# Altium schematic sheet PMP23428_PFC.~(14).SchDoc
size 431 x 279 mm; Date: Not shown in title block; ApprovedBy: Not shown in title block; CheckedBy: Not shown in title block; Author: Not shown in title block; CompanyName: Not shown in title block; Engineer: Not shown in title block; Organization: Not shown in title block; Address1: Not shown in title block; Address2: Not shown in title block; Address3: Not shown in title block; Address4: Not shown in title block; DocumentNumber: 1; Revision: Use project parameter SCH_Rev; SheetNumber: 1; SheetTotal: 4; PageSetup: Record=PageOptions¦CenterHorizontal=True¦CenterVertical=True¦PrintScale=1.00¦XCorrection=1.00¦YCorrection=1.00¦PrintKind=0¦BorderSize=5000000¦LeftOffset=0¦BottomOffset=0¦Orientation=2¦PaperLength=1000¦PaperWidth=1000¦Scale=100¦PaperSource=15¦PrintQuality=600¦MediaType=1¦DitherType=10¦PaperKind=Letter¦PrintScaleMode=1
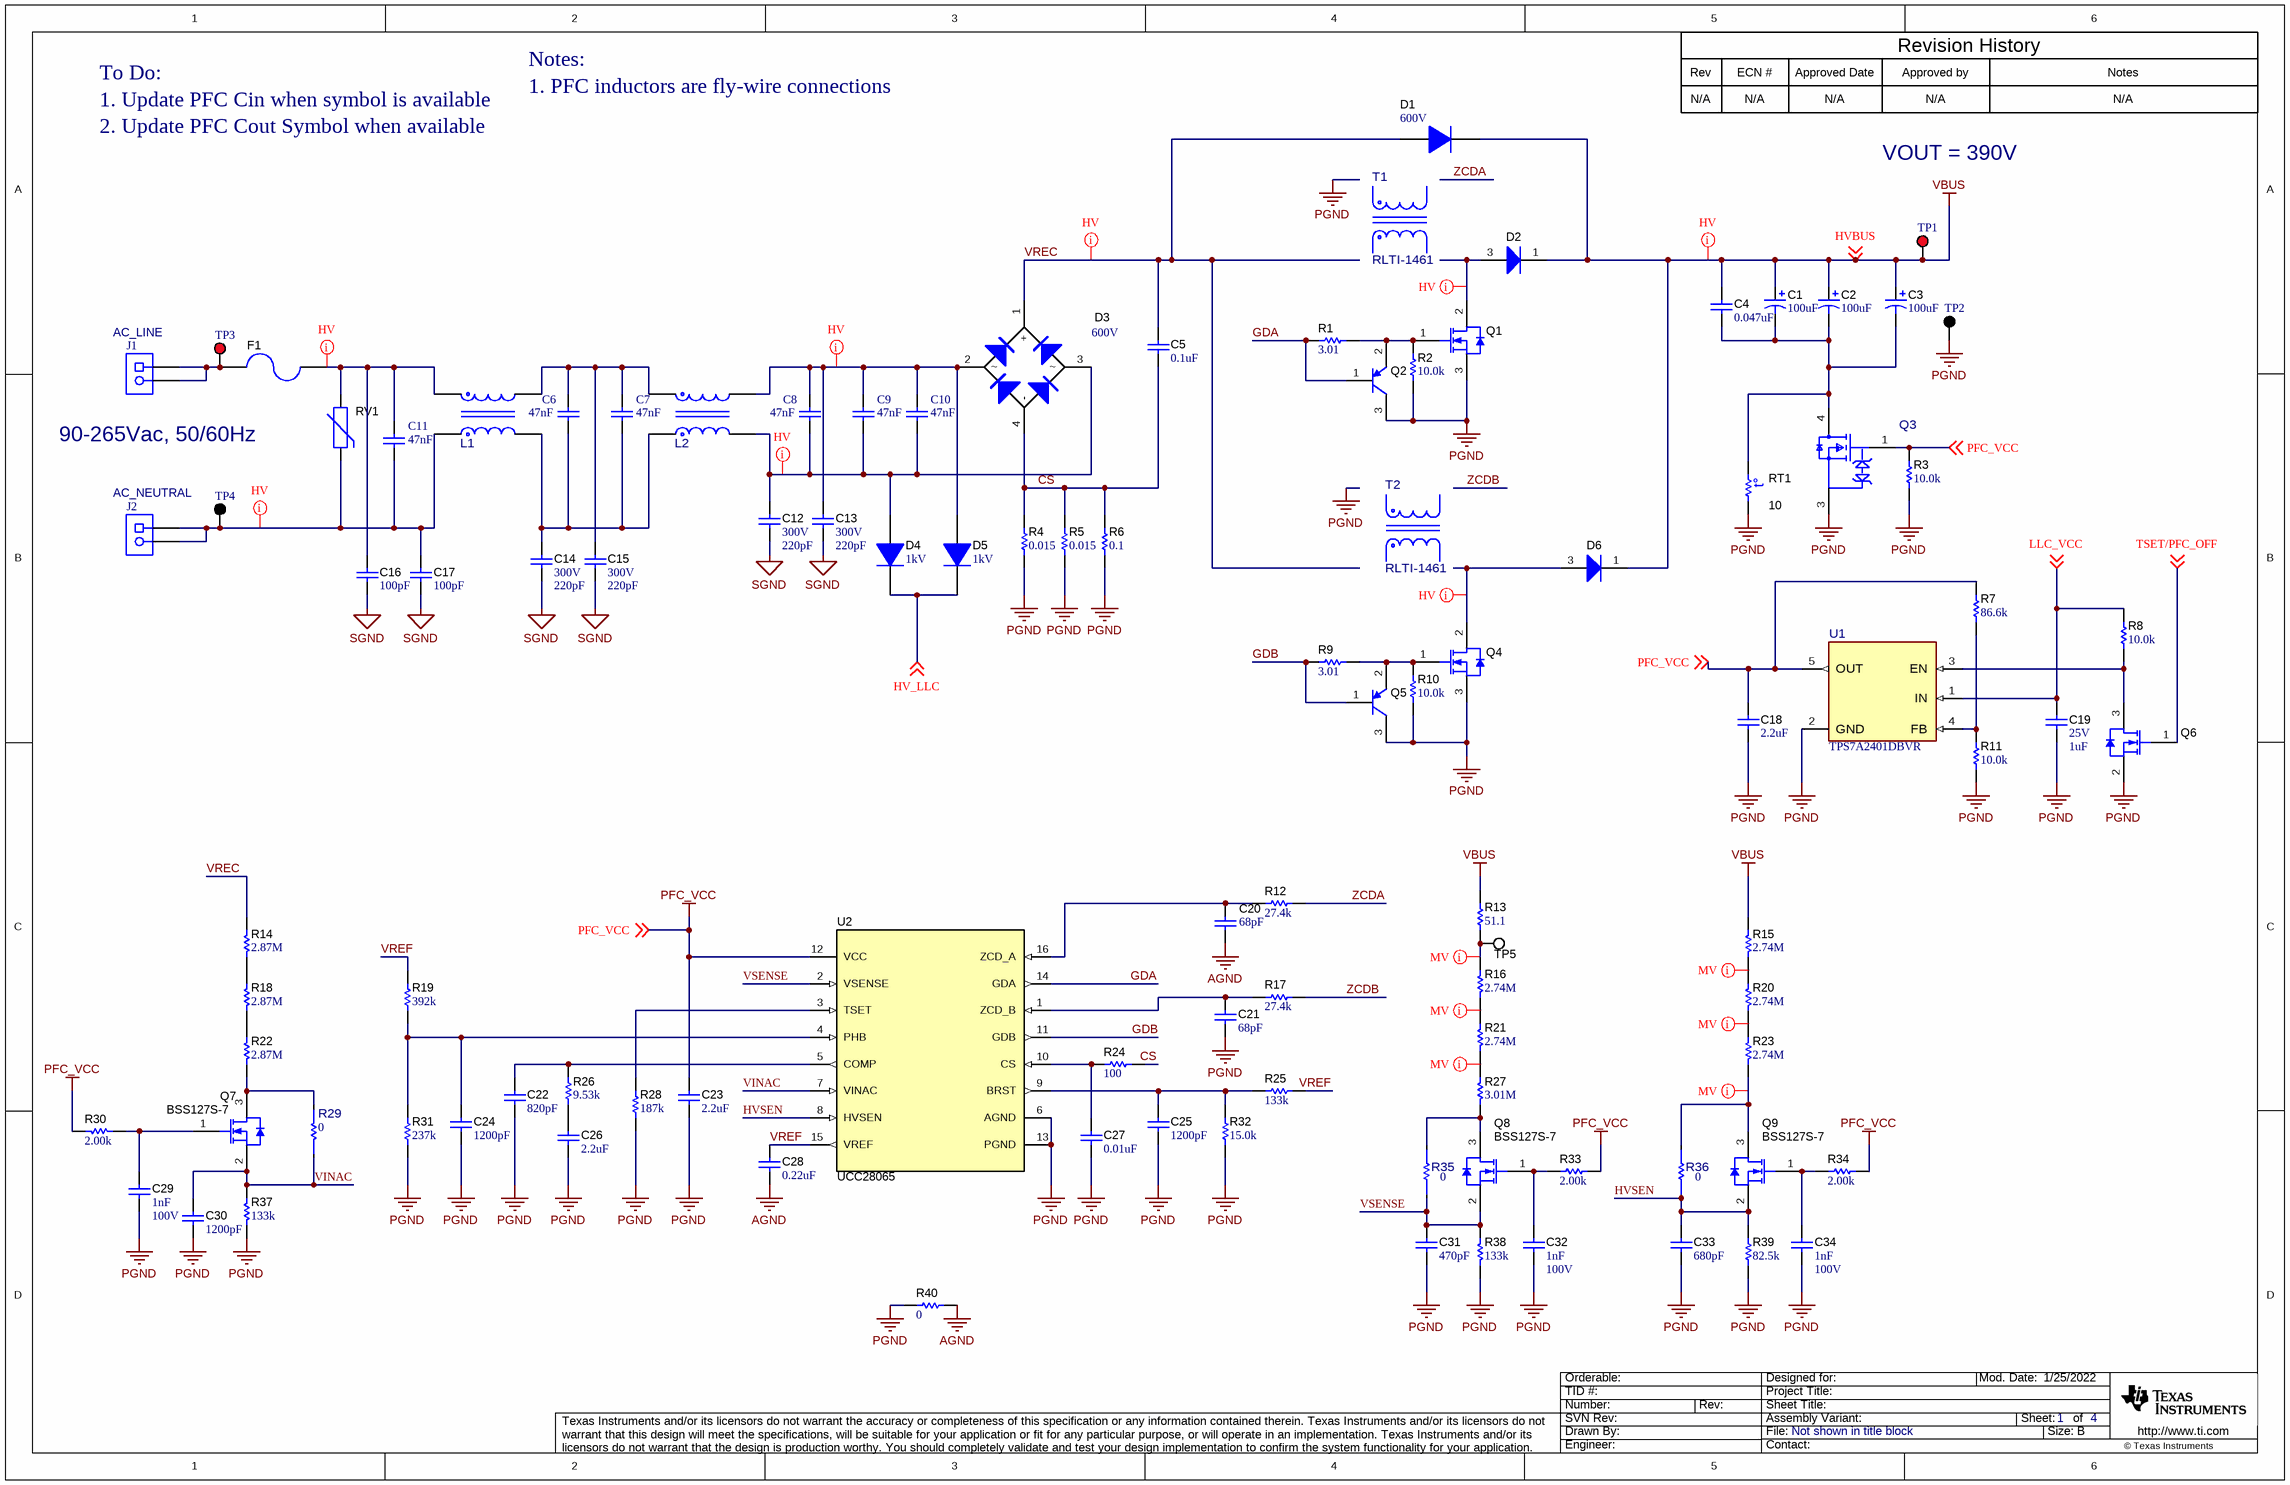
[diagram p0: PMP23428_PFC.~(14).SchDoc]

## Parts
C1  ValueDisplayed: 100uF  [KXG_1800x4000_horizontalUp]  (hidden comment: Cap_Polarized)
C2  ValueDisplayed: 100uF  [KXG_1800x4000_horizontalUp]  (hidden comment: Cap_Polarized)
C3  ValueDisplayed: 100uF  [KXG_1800x4000_horizontalDown]  (hidden comment: Cap_Polarized)
C4  ValueDisplayed: 0.047uF  [ECQE_1200x1450x650]  (hidden comment: Capacitor)
C5  ValueDisplayed: 0.1uF  [CAPRR1500W60L1750T550H1250]  (hidden comment: Capacitor)
C6  Cap_F: 47nF  [WCAP-FTX2_L13W4.5H9.5]  (hidden comment: 890324023015)
C7  Cap_F: 47nF  [WCAP-FTX2_L13W4.5H9.5]  (hidden comment: 890324023015)
C8  Cap_F: 47nF  [WCAP-FTX2_L13W4.5H9.5]  (hidden comment: 890324023015)
C9  Cap_F: 47nF  [WCAP-FTX2_L13W4.5H9.5]  (hidden comment: 890324023015)
C10  Cap_F: 47nF  [WCAP-FTX2_L13W4.5H9.5]  (hidden comment: 890324023015)
C11  Cap_F: 47nF  [WCAP-FTX2_L13W4.5H9.5]  (hidden comment: 890324023015)
C12  VDC_V: 300V  ValueDisplayed: 220pF  [B_800x700x800]  (hidden comment: DE6B3KJ221KN3A)
C13  VDC_V: 300V  ValueDisplayed: 220pF  [B_800x700x800]  (hidden comment: DE6B3KJ221KN3A)
C14  VDC_V: 300V  ValueDisplayed: 220pF  [B_800x700x800]  (hidden comment: DE6B3KJ221KN3A)
C15  VDC_V: 300V  ValueDisplayed: 220pF  [B_800x700x800]  (hidden comment: DE6B3KJ221KN3A)
C16  ValueDisplayed: 100pF  [KY_700x500x1000]  (hidden comment: DE2B3KY101KN3AU02F)
C17  ValueDisplayed: 100pF  [KY_700x500x1000]  (hidden comment: DE2B3KY101KN3AU02F)
C18  ValueDisplayed: 2.2uF  [0805_HV]  (hidden comment: Capacitor)
C19  VDC_V: 25V  ValueDisplayed: 1uF  [0603]  (hidden comment: C1608X5R1E105K080AC)
C20  ValueDisplayed: 68pF  [0805_HV]  (hidden comment: Capacitor)
C21  ValueDisplayed: 68pF  [0805_HV]  (hidden comment: Capacitor)
C22  ValueDisplayed: 820pF  [0805_HV]  (hidden comment: Capacitor)
C23  ValueDisplayed: 2.2uF  [0805_HV]  (hidden comment: Capacitor)
C24  ValueDisplayed: 1200pF  [0805_HV]  (hidden comment: Capacitor)
C25  ValueDisplayed: 1200pF  [0805_HV]  (hidden comment: Capacitor)
C26  ValueDisplayed: 2.2uF  [0805_HV]  (hidden comment: Capacitor)
C27  ValueDisplayed: 0.01uF  [0805_HV]  (hidden comment: Capacitor)
C28  ValueDisplayed: 0.22uF  [1206]  (hidden comment: Capacitor)
C29  Cap_F: 1nF  VDC_V: 100V  [0603]  (hidden comment: C1608X7R2A102K080AA)
C30  ValueDisplayed: 1200pF  [0805_HV]  (hidden comment: Capacitor)
C31  ValueDisplayed: 470pF  [0805_HV]  (hidden comment: Capacitor)
C32  Cap_F: 1nF  VDC_V: 100V  [0603]  (hidden comment: C1608X7R2A102K080AA)
C33  ValueDisplayed: 680pF  [0805_HV]  (hidden comment: Capacitor)
C34  Cap_F: 1nF  VDC_V: 100V  [0603]  (hidden comment: C1608X7R2A102K080AA)
D1  Vr_V: 600V  [SMC]  (hidden comment: DIODE)
D2  MUR860G  [TO-220AC_HORIZ]  (value not drawn)
D3  Vr_V: 600V  [GBU_Horizontal_Down_Standoff2300]  (hidden comment: GBU6J)
D4  Vr_V: 1kV  [DO-41]  (hidden comment: 1N4007-E3/73)
D5  Vr_V: 1kV  [DO-41]  (hidden comment: 1N4007-E3/73)
D6  MUR860G  [TO-220AC_HORIZ]  (value not drawn)
F1  0216008.MXEP  [FUSE_0216]  (value not drawn)
J1  Receptacle_2x1  [On-Shore_ED120_2DS]  (value not drawn)
J2  Receptacle_2x1  [On-Shore_ED120_2DS]  (value not drawn)
L1  7448680120  [FP-7448680120_PTH_CMC_27MM5_25MM0-MFG]  (value not drawn)
L2  7448680120  [FP-7448680120_PTH_CMC_27MM5_25MM0-MFG]  (value not drawn)
Q1  IPP60R099CPXKSA1  [TO-220AB_Horizontal_100mil_Standoff2300]  (value not drawn)
Q2  FMMT718TA  [SOT-23]  (value not drawn)
Q3  STB18N60DM2  [FP-STB18N60DM2_D2PAK-MFG]  (value not drawn)
Q4  IPP60R099CPXKSA1  [TO-220AB_Horizontal_100mil_Standoff2300]  (value not drawn)
Q5  FMMT718TA  [SOT-23]  (value not drawn)
Q6  2N7002-7-F  [SOT-23]  (value not drawn)
Q7  BSS127S-7  [SOT-23]
Q8  BSS127S-7  [SOT-23]
Q9  BSS127S-7  [SOT-23]
R1  ValueDisplayed: 3.01  [0603]  (hidden comment: RC0603FR-073R01L)
R2  ValueDisplayed: 10.0k  [0805_HV]  (hidden comment: Resistor)
R3  ValueDisplayed: 10.0k  [0805_HV]  (hidden comment: Resistor)
R4  ValueDisplayed: 0.015  [2010]  (hidden comment: Resistor)
R5  ValueDisplayed: 0.015  [2010]  (hidden comment: Resistor)
R6  ValueDisplayed: 0.1  [2010]  (hidden comment: CRM2010-FX-R100ELF)
R7  ValueDisplayed: 86.6k  [0603]  (hidden comment: RC0603FR-0786K6L)
R8  ValueDisplayed: 10.0k  [0603]  (hidden comment: M55342K12B10E0T)
R9  ValueDisplayed: 3.01  [0603]  (hidden comment: RC0603FR-073R01L)
R10  ValueDisplayed: 10.0k  [0805_HV]  (hidden comment: Resistor)
R11  ValueDisplayed: 10.0k  [0603]  (hidden comment: M55342K12B10E0T)
R12  ValueDisplayed: 27.4k  [0603]  (hidden comment: RC0603FR-0727K4L)
R13  ValueDisplayed: 51.1  [0805_HV]  (hidden comment: Resistor)
R14  ValueDisplayed: 2.87M  [0805_HV]  (hidden comment: Resistor)
R15  ValueDisplayed: 2.74M  [0805_HV]  (hidden comment: Resistor)
R16  ValueDisplayed: 2.74M  [0805_HV]  (hidden comment: Resistor)
R17  ValueDisplayed: 27.4k  [0603]  (hidden comment: RC0603FR-0727K4L)
R18  ValueDisplayed: 2.87M  [0805_HV]  (hidden comment: Resistor)
R19  ValueDisplayed: 392k  [0603]  (hidden comment: RC0603FR-07392KL)
R20  ValueDisplayed: 2.74M  [0805_HV]  (hidden comment: Resistor)
R21  ValueDisplayed: 2.74M  [0805_HV]  (hidden comment: Resistor)
R22  ValueDisplayed: 2.87M  [0805_HV]  (hidden comment: Resistor)
R23  ValueDisplayed: 2.74M  [0805_HV]  (hidden comment: Resistor)
R24  ValueDisplayed: 100  [0805_HV]  (hidden comment: Resistor)
R25  ValueDisplayed: 133k  [0805_HV]  (hidden comment: CRCW0805133KFKEA)
R26  ValueDisplayed: 9.53k  [0805_HV]  (hidden comment: Resistor)
R27  ValueDisplayed: 3.01M  [0805_HV]  (hidden comment: Resistor)
R28  ValueDisplayed: 187k  [0603]  (hidden comment: CRCW0603187KFKEA)
R29  value 0  [FP-RMCF1206ZT0R00_1206-MFG]  (hidden comment: RMCF1206ZT0R00)
R30  ValueDisplayed: 2.00k  [0603]  (hidden comment: RC0603FR-072KL)
R31  ValueDisplayed: 237k  [0603]  (hidden comment: RC0603FR-07237KL)
R32  ValueDisplayed: 15.0k  [0805_HV]  (hidden comment: CRCW080515K0FKEA)
R33  ValueDisplayed: 2.00k  [0603]  (hidden comment: RC0603FR-072KL)
R34  ValueDisplayed: 2.00k  [0603]  (hidden comment: RC0603FR-072KL)
R35  value 0  [FP-RMCF1206ZT0R00_1206-MFG]  (hidden comment: RMCF1206ZT0R00)
R36  value 0  [FP-RMCF1206ZT0R00_1206-MFG]  (hidden comment: RMCF1206ZT0R00)
R37  ValueDisplayed: 133k  [0805_HV]  (hidden comment: CRCW0805133KFKEA)
R38  ValueDisplayed: 133k  [0805_HV]  (hidden comment: Resistor)
R39  ValueDisplayed: 82.5k  [0805_HV]  (hidden comment: Resistor)
R40  ValueDisplayed: 0  [2512]  (hidden comment: Resistor)
RT1  value 10  [S153]  (hidden comment: B57153S0100M000)
RV1  Varistor_MetalOxide  [VAR_S10K275E2]  (value not drawn)
T1  RLTI-1461  [FP-RLTI-1461_PFC_IND_1IN25_3IN0-MFG]
T2  RLTI-1461  [FP-RLTI-1461_PFC_IND_1IN25_3IN0-MFG]
TP1  5010  [Keystone5010]  (value not drawn)
TP2  5011  [Keystone5011]  (value not drawn)
TP3  5010  [Keystone5010]  (value not drawn)
TP4  5011  [Keystone5011]  (value not drawn)
TP5  5002  [Keystone5002]  (value not drawn)
U1  TPS7A2401DBVR  [DBV0005A-MFG]
U2  UCC28065  [D0016A_N]

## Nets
AGND: C20.2 C28.2 R40.1
PFC_VCC: C18.2 C23.2 Q3.1(G) R3.2 R7.1 R30.2 R33.2 R34.2 U1.5(OUT) U2.12(VCC) ; off-sheet PFC_VCC
PGND: C18.1 C19.2 C21.1 C22.1 C23.1 C24.2 C25.2 C26.2 C27.2 C29.2 C30.1 C31.2 C32.2 C33.2 C34.2 Q1.3(S) Q2.3(C) Q3.3(S) Q4.3(S) Q5.3(C) Q6.2(S) R2.1 R3.1 R4.1 R5.1 R6.1 R10.1 R11.1 R28.1 R31.1 R32.1 R37.1 R38.1 R39.1 R40.2 RT1.1 TP2.1 U1.2(GND) U2.6(AGND) U2.13(PGND)
SGND: C12.2 C13.2 C14.2 C15.2 C16.2 C17.2
VBUS: C1.1(+) C2.1(+) C3.1(+) C4.1 D1.1(K) D2.1(K) D6.1(K) R13.2 R15.2 TP1.1 ; off-sheet HVBUS  [also labelled HVBUS]
CS: C5.2 D3.4(-) R4.2 R5.2 R6.2 R24.2
GDA: Q2.1(B) R1.1 U2.14(GDA)
GDB: Q5.1(B) R9.1 U2.11(GDB)
HV_LLC: D4.1(K) D5.1(K) ; off-sheet HV_LLC
HVSEN: C33.1 Q9.2(S) R36.1 R39.2 U2.8(HVSEN)
LLC_VCC: C19.1 R8.2 U1.1(IN) ; off-sheet LLC_VCC
TSET/PFC_OFF: Q6.1(G) ; off-sheet TSET/PFC_OFF
VINAC: C30.2 Q7.2(S) R29.1 R37.2 U2.7(VINAC)
VREC: C5.1 D1.2(A) D3.1(+) R14.1
VREF: C28.1 R19.2 R25.2 U2.15(VREF)
VSENSE: C31.1 Q8.2(S) R35.1 R38.2 U2.2(VSENSE)
ZCDA: R12.2
ZCDB: R17.2
NetC1_2: C1.2(-) C2.2(-) C3.2(-) C4.2 Q3.4(D) RT1.2
NetC6_1: C6.1 C7.1 C14.1 L1.2 L2.1
NetC6_2: C6.2 C7.2 C15.1 L1.3 L2.4
NetC8_1: C8.1 C9.1 C10.1 C12.1 D3.3 D4.2(A) L2.2
NetC8_2: C8.2 C9.2 C10.2 C13.1 D3.2 D5.2(A) L2.3
NetC11_1: C11.1 C17.1 J2.1 J2.2 L1.1 RV1.2 TP4.1
NetC11_2: C11.2 C16.1 F1.1 L1.4 RV1.1
NetC20_1: C20.1 R12.1 U2.16(ZCD_A)
NetC21_2: C21.2 R17.1 U2.1(ZCD_B)
NetC22_2: C22.2 R26.2 U2.5(COMP)
NetC24_1: C24.1 R19.1 R31.2 U2.4(PHB)
NetC25_1: C25.1 R25.1 R32.2 U2.9(BRST)
NetC26_1: C26.1 R26.1
NetC27_1: C27.1 R24.1 U2.10(CS)
NetC29_1: C29.1 Q7.1(G) R30.1
NetC32_1: C32.1 Q8.1(G) R33.1
NetC34_1: C34.1 Q9.1(G) R34.1
NetD2_3: D2.3(A) Q1.2(D)
NetD6_3: D6.3(A) Q4.2(D)
NetF1_2: F1.2 J1.1 J1.2 TP3.1
NetQ1_1: Q1.1(G) Q2.2(E) R1.2 R2.2
NetQ4_1: Q4.1(G) Q5.2(E) R9.2 R10.2
NetQ6_3: Q6.3(D) R8.1 U1.3(EN)
NetQ7_3: Q7.3(D) R22.1 R29.2
NetQ8_3: Q8.3(D) R27.2 R35.2
NetQ9_3: Q9.3(D) R23.1 R36.2
NetR7_2: R7.2 R11.2 U1.4(FB)
NetR13_1: R13.1 R16.1 TP5.1
NetR14_2: R14.2 R18.1
NetR15_1: R15.1 R20.2
NetR16_2: R16.2 R21.1
NetR18_2: R18.2 R22.2
NetR20_1: R20.1 R23.2
NetR21_2: R21.2 R27.1
NetR28_2: R28.2 U2.3(TSET)

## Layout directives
net class HV: NetC8_1, NetC8_2, NetC11_1, NetC11_2, NetD2_3, NetD6_3, VBUS, VREC
net class MV: NetQ9_3, NetR13_1, NetR15_1, NetR16_2, NetR20_1, NetR21_2

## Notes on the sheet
- To Do:
- Notes:
- 1. PFC inductors are fly-wire connections
- Rev
- N/A
- ECN #
- Approved Date
- Approved by
- Revision History
- Notes
- 1. Update PFC Cin when symbol is available
- 2. Update PFC Cout Symbol when available
- VOUT = 390V
- (near J1) AC_LINE
- 90-265Vac, 50/60Hz
- (near J2) AC_NEUTRAL

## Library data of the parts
C1-C3 = CMP-0010042-2: CAP, AL, 100 uF, 450 V, +/- 20%, TH; PartNumber: EKXG451ELL101MM40S; Manufacturer: Chemi-Con; Polarized: Y; CompType: Capacitor; Value: 100uF; U/M: EA; Cap_F: 100µF; Value1: Unknown; VDC_V: 450V; IRMS_A: 8dA; TaMin_C: -25°C; TaMax_C: 105°C; Cap_Case: 18x40mm; SizeAreaWB_mm2: 400; SizeArea_mm2: 324; SizeX_mm: 18; SizeZ_mm: 41.5; AEC Category: Q200; AEC Qualified: N
C4 = CMP-0012494-3: CAP, Film, 0.047 uF, 630 V, +/- 10%, TH; PartNumber: ECQ-E6473KF; Manufacturer: Panasonic; Polarized: N; Cap_F: 47nF; Value1: Unknown; VDC_V: 630V; TaMin_C: -40°C; TaMax_C: 105°C; Cap_Case: 12x14.5x6.5mm; SizeAreaWB_mm2: 119; SizeArea_mm2: 78; SizeX_mm: 12; SizeY_mm: 6.5; SizeZ_mm: 14.5; AEC Category: Q200
C5 = CMP-0012496-3: CAP, Film, 0.1 uF, 275 V, +/- 20%, TH; PartNumber: ECQ-U2A104ML; Manufacturer: Panasonic; Polarized: N; Value: 0.1uF; Cap_F: 100nF; Value1: Unknown; VDC_V: 275V; TaMin_C: -40°C; TaMax_C: 100°C; Cap_Case: Radial 17.5x5.5x12.5; AEC Category: Q200
C6-C11 = CMP-0112456-1: WCAP-FTX2 Film Capacitor, THT, L13 x W4.5 x H9.5mm, 47nF, 275V; Manufacturer: Wurth Elektronik; Capacitance Tolerance: +/-10%; Dissipation Factor @100kHz: 0.5%; Dissipation Factor @10kHz: 0.1%; Insulation Resistance: 30000MOhm; Pitch: 10mm; Rate of Voltage Rise: 300V/us; Technical Reference: MX2P010473K275ASPB15000
C12-C15 = CMP-0009612-2: CAP, CERM, 220 pF, 300 V, +/- 10%, B, TH, 2- Leads, Body 8x7mm, Pin Spacing 7.5mm; Manufacturer: MuRata; TaMin_C: -40°C; Polarized: N; SizeAreaWB_mm2: 90; Value1: Unknown; U/M: EA; Value: 220pF; TaMax_C: 125°C; SizeZ_mm: 11; SizeX_mm: 8; SizeY_mm: 7; Cap_Case: 8x7x8mm; SizeArea_mm2: 56; AEC Category: Q200
C16 C17 = CMP-0009606-4: CAP, CERM, 100 pF, X1 250 VAC/Y2 300 VAC, +/- 10%, B, TH; Manufacturer: MuRata; TaMin_C: -25°C; Polarized: N; SizeAreaWB_mm2: 66.5; Value1: Unknown; U/M: EA; Value: 100pF; TaMax_C: 85°C; SizeZ_mm: 10; SizeX_mm: 7.5; SizeY_mm: 5; Cap_Case: 7x5x10mm; SizeArea_mm2: 37.5; AEC Category: Q200; AC_Safety: X1Y2; VAC_X: 250V; VAC_Y: 300V
C18 C23 C26 = CMP-0007877-2: CAP, CERM, 2.2 uF, 50 V, +/- 10%, X7R, 0805; PartNumber: C2012X7R1H225K125AC; Manufacturer: TDK; Polarized: N; Value: 2.2uF; U/M: EA; Cap_F: 2.2µF; ESR_ohm: 3.66m; Value1: 0.00366 ohm; VDC_V: 50V; IRMS_A: 3.41207A; TaMin_C: -55°C; TaMax_C: 125°C; Cap_Case: 0805; SizeArea_mm2: 2.5; SizeAreaWB_mm2: 6.75; SizeX_mm: 2; SizeY_mm: 1.25; SizeZ_mm: 1.45; AEC Category: Q200
C19 = CMP-0007006-5: CAP, CERM, 1 uF, 25 V, +/- 10%, X5R, 0603; Manufacturer: TDK; TaMin_C: -55°C; Polarized: N; SizeAreaWB_mm2: 4.68; Value1: Unknown; U/M: EA; Value: 1uF; TaMax_C: 85°C; SizeZ_mm: 1; SizeX_mm: 1.6; SizeY_mm: 0.8; SizeArea_mm2: 1.28; Cap_F: 1µF; AEC Category: Q200
C20 C21 = CMP-0007622-2: CAP, CERM, 68 pF, 50 V, +/- 5%, C0G/NP0, 0805; PartNumber: 08055A680JAT2A; Manufacturer: AVX; Polarized: N; Value: 68pF; U/M: EA; ESR_ohm: 4.5d; Value1: 0.45 ohm; VDC_V: 50V; TaMin_C: -55°C; TaMax_C: 125°C; Cap_Case: 0805; SizeArea_mm2: 2.5; SizeAreaWB_mm2: 6.75; SizeX_mm: 2; SizeY_mm: 1.25; SizeZ_mm: 1.45; AEC Category: Q200
C22 = CMP-0008153-2: CAP, CERM, 820 pF, 25 V, +/- 10%, X7R, 0805; PartNumber: GRM216R71E821KA01D; Manufacturer: MuRata; Polarized: N; Value: 820pF; U/M: EA; Value1: Unknown; VDC_V: 25V; TaMin_C: -55°C; TaMax_C: 125°C; Cap_Case: 0805; SizeArea_mm2: 2.5; SizeAreaWB_mm2: 6.75; SizeX_mm: 2; SizeY_mm: 1.25; SizeZ_mm: 1.45; AEC Category: Q200
C24 C25 C30 = CMP-0008142-2: CAP, CERM, 1200 pF, 25 V, +/- 10%, X7R, 0805; PartNumber: GRM216R71E122KA01D; Manufacturer: MuRata; Polarized: N; Value: 1200pF; U/M: EA; Cap_F: 1.2nF; Value1: Unknown; VDC_V: 25V; TaMin_C: -55°C; TaMax_C: 125°C; Cap_Case: 0805; SizeArea_mm2: 2.5; SizeAreaWB_mm2: 6.75; SizeX_mm: 2; SizeY_mm: 1.25; SizeZ_mm: 1.45; AEC Category: Q200
C27 = CMP-0007629-2: CAP, CERM, 0.01 uF, 50 V, +/- 5%, X7R, 0805; PartNumber: 08055C103JAT2A; Manufacturer: AVX; Polarized: N; Value: 0.01uF; U/M: EA; Cap_F: 10nF; ESR_ohm: 0.078; Value1: 0.078 ohm; VDC_V: 50V; TaMin_C: -55°C; TaMax_C: 125°C; Cap_Case: 0805; SizeArea_mm2: 2.5; SizeAreaWB_mm2: 6.75; SizeX_mm: 2; SizeY_mm: 1.25; SizeZ_mm: 1.45; AEC Category: Q200
C28 = CMP-0008995-2: CAP, CERM, 0.22 uF, 50 V, +/- 10%, X7R, 1206; PartNumber: GRM31MR71H224KA01L; Manufacturer: MuRata; Polarized: N; Value: 0.22uF; U/M: EA; Cap_F: 220nF; Value1: Unknown; VDC_V: 50V; TaMin_C: -55°C; TaMax_C: 125°C; SizeArea_mm2: 5.12; SizeAreaWB_mm2: 10.92; SizeX_mm: 3.2; SizeY_mm: 1.6; SizeZ_mm: 1.35; AEC Category: Q200
C29 C32 C34 = CMP-0007053-4: CAP, CERM, 1000 pF, 100 V, +/- 10%, X7R, 0603; Manufacturer: TDK; TaMin_C: -55°C; Polarized: N; SizeAreaWB_mm2: 4.68; Value1: Unknown; U/M: EA; Value: 1000pF; TaMax_C: 125°C; SizeZ_mm: 1; SizeX_mm: 1.6; SizeY_mm: 0.8; SizeArea_mm2: 1.28; AEC Category: Q200
C31 = CMP-0008150-2: CAP, CERM, 470 pF, 25 V, +/- 10%, X7R, 0805; PartNumber: GRM216R71E471KA01D; Manufacturer: MuRata; Polarized: N; Value: 470pF; U/M: EA; Value1: Unknown; VDC_V: 25V; TaMin_C: -55°C; TaMax_C: 125°C; Cap_Case: 0805; SizeArea_mm2: 2.5; SizeAreaWB_mm2: 6.75; SizeX_mm: 2; SizeY_mm: 1.25; SizeZ_mm: 1.45; AEC Category: Q200
C33 = CMP-0007693-2: CAP, CERM, 680 pF, 25 V, +/- 10%, X7R, 0805; PartNumber: 885012207059; Manufacturer: Wurth Elektronik; Polarized: N; Value: 680pF; U/M: EA; Value1: Unknown; VDC_V: 25V; TaMin_C: -55°C; TaMax_C: 125°C; Cap_Case: 0805; SizeArea_mm2: 2.5; SizeAreaWB_mm2: 6.75; SizeX_mm: 2; SizeY_mm: 1.25; SizeZ_mm: 1.45; AEC Category: Q200
D1 = CMP-0076905-1: Diode, Ultrafast, 600 V, 3 A, SMC; PartNumber: MURS360T3G; Manufacturer: ON Semiconductor; U/M: EA; Vf_V: 1.25V; Value: 600V; Value1: 3A; TJmax_C: 175°C; RJC_CperW: 11.0; SizeAreaWB_mm2: 83.2686; SizeArea_mm2: 50.5686; SizeX_mm: 8.13; SizeY_mm: 6.22; SizeZ_mm: 2.6; AEC Category: Q101; Green_Lifecycle: Active; Green_REACh: Passed
D2 D6 = CMP-0029037-2: Diode, Ultrafast, 600 V, 8 A, TH; Manufacturer: ON Semiconductor; TJmax_C: 175°C; Green_Lifecycle: Not Set; SizeX_mm: 10.15; SizeAreaWB_mm2: 78.975; RJC_CperW: 4.75; SizeArea_mm2: 45.675; Green_REACh: Incomplete; Vf_V: 980mV; Value2: 0.98V; Io_A: 8A; SizeY_mm: 4.5; AEC Category: Q101; SizeZ_mm: 23; Value: 600V
D3 = CMP-0029269-2: Diode, Switching-Bridge, 600 V, 6 A, TH; Manufacturer: Fairchild Semiconductor; U/M: EA; Vf_V: 1V; Value: 600V; Value1: 6A; TJmax_C: 150°C; RJC_CperW: 3.1; SizeAreaWB_mm2: 130.5915; SizeArea_mm2: 75.6315; SizeX_mm: 22.05; SizeY_mm: 3.43; SizeZ_mm: 21.55; AEC Category: Q101; AEC Qualified: N; Green_Lifecycle: Active; Green_REACh: Passed
D4 D5 = CMP-0029188-2: Diode, P-N, 1000 V, 1 A, TH; Manufacturer: Vishay-Semiconductor; Io_A: 1A; SizeAreaWB_mm2: 43.424; TJmax_C: 150°C; Value: 1000V; SizeZ_mm: 23.4; SizeX_mm: 7.2; SizeY_mm: 2.72; Vf_V: 1.1V; SizeArea_mm2: 19.584; AEC Qualified: N; AEC Category: Q101
F1 = CMP-0079917-1: Fuse, 8 A, 250 VAC, TH; Manufacturer: Littelfuse; VAC_V: 250V; Rtyp_Ohm: 0.0123; MeltingTyp: 64.315; Irating_A: 8A; Interrupt_AC: 1.5kA
J1 J2 = CMP-0074910-1: Terminal Block, 5.08 mm, 2x1, Brass, TH; PartNumber: ED120/2DS; Manufacturer: On-Shore Technology; Pitch_mm: 5.08; Gender: Female; Shrouded: N; Row_Count: 1; Current_A: 15A; Voltage_V: 300V; Cert_CULUS: Y; Green_Lifecycle: Not Set; Green_REACh: Incomplete; CNHeader: False; CT: True
L1 L2 = CMP-0120034-1: 330 µH @ 10 kHz 2 Line Common Mode Choke Through Hole 12A DCR 6mOhm; Manufacturer: Wurth Electronics; DCR_ohm: 6m; Ind_H: 330µH; SizeZ_mm: 10mm; AEC Qualified: No; TaMax_C: +60°C; TaMin_C: -40°C; Test Frequency: 10kHz; Tolerance_%: 40%
Q1 Q4 = CMP-0001172-3: MOSFET, N-CH, 600 V, 31 A, TO-220AB; Alternate Manufacturer: None; Manufacturer: Infineon Technologies; SizeZ_mm: 19.4; ChType: N; Value2: 60 nC; VdsMax_V: 600V; SizeX_mm: 10.2; SizeY_mm: 4.5; Vgs_V: 20V; Value: 600V; SizeArea_mm2: 45.9; AEC Category: Q101; IdsMax_A: 31A; SizeAreaWB_mm2: 79.3; U/M: EA; QgTyp_nC: 60
Q2 Q5 = CMP-0000330-2: Transistor, PNP, 20 V, 1.5 A, SOT-23; Manufacturer: Diodes Inc.; TaMax_C: 150°C; Value2: 6; Value1: 1.5 A; Vcesat1_V: 20V; SizeX_mm: 2.5; SizeY_mm: 3; TaMin_C: -55°C; IcRated_A: 1.5A; CompType: BJT; SizeZ_mm: 1.1; Value: 20 V; SizeArea_mm2: 7.5; NPN: 0; PNP: 1; AEC Category: Q101; SizeAreaWB_mm2: 14; U/M: EA
Q3 = CMP-0084087-1: N-Channel 600V 12A (Tc) 90W (Tc) Surface Mount D2PAK; Manufacturer: STMicroelectronics; Rdson45_ohm: 0.26Ω; Threshold Vgs Max: 5V; Input Capacitace At Vds: 800pF @ 100V; Turn On Delay Time: 13.5ns; AEC Qualified: No; ChMode: False; Symbol Name: SYM-STB18N60DM2; Max Forward Diode Voltage: 1.6V; Vgs_V: 25V; Pulse Drain Current: 48A; Standoff Height: 0.03mm; Reverse Recovery Time: 125ns; Number Of N Channels: 1; Turn Off Delay Time: 9.5ns; QgTyp_nC: 20nC @ 10V; TJmax_C: +150°C; Reverse Recovery Charge: 675nC; Power_W: 110W; SizeZ_mm: 4.83mm; Threshold Vgs Min: 3V
Q6 = CMP-0000769-1: MOSFET, N-CH, 60 V, 0.17 A, SOT-23; Alternate Manufacturer: None; Manufacturer: Diodes Inc.; SizeZ_mm: 1.1; ChType: N; Value2: 223 nC; Value1: 7; VdsMax_V: 60V; SizeX_mm: 2.5; SizeY_mm: 3; Vgs_V: 20V; Value: 60V; Rdson45_ohm: 7.5; AEC Category: Q101; IdsMax_A: 1.7dA; SizeAreaWB_mm2: 14; U/M: EA; QgTyp_nC: 223
Q7-Q9 = CMP-0001149-3: MOSFET, N-CH, 600 V, 0.05 A, SOT-23; Alternate Manufacturer: None; Manufacturer: Diodes Inc.; SizeZ_mm: 1.1; ChType: N; Value2: 1.08 nC; VdsMax_V: 600V; SizeX_mm: 2.5; SizeY_mm: 3; Vgs_V: 20V; QgTyp_nC: 1.08; Value: 600V; SizeArea_mm2: 7.5; AEC Category: Q101; IdsMax_A: 50mA; SizeAreaWB_mm2: 14; U/M: EA
R1 R9 = CMP-0023093-5: RES, 3.01, 1%, 0.1 W, 0603; Manufacturer: Yageo; Power_W: 100mW; TempCo: 200 ppm/C; Value_Code: 3R01; Value: 3.01; EIA_Code: E96; SizeX_mm: 1.6; SizeY_mm: 0.8; SizeZ_mm: 1; Value2: 0.1W; SizeArea_mm2: 1.28; AEC Qualified: N; VDC_V: 75V; AEC Category: Q200; SizeAreaWB_mm2: 4.68
R2 R3 R10 = CMP-0020842-3: RES, 10.0 k, 1%, 0.125 W, AEC-Q200 Grade 0, 0805; PartNumber: CRCW080510K0FKEA; Manufacturer: Vishay-Dale; Value: 10.0k; Res_ohm: 10k; Value_Code: 10k0; Power_W: 125mW; Value2: 0.125W; VDC_V: 150V; TempCo: 100 ppm/C; SizeArea_mm2: 2.5; SizeX_mm: 2; SizeY_mm: 1.25; SizeZ_mm: 1.45; EIA_Code: E96; AEC Category: Q200; AEC Qualified: Y; AEC Grade: 0
R4 R5 = CMP-0016558-2: RES, 0.015, 1%, 0.5 W, 2010; PartNumber: WSL2010R0150FEA; Manufacturer: Vishay-Dale; Value: 0.015; Value_Code: R015; Power_W: 500mW; Value2: 0.5W; TempCo: 75 ppm/C; SizeArea_mm2: 12.5; SizeX_mm: 5; SizeY_mm: 2.5; SizeZ_mm: 1.66; EIA_Code: E96; U/M: EA; AEC Category: Q200
R6 = CMP-0016505-2: RES, 0.1, 1%, 1 W, 2010; Manufacturer: Bourns; Power_W: 1W; TempCo: 150 ppm/C; Value_Code: R100; U/M: EA; Value: 0.1; EIA_Code: E96; Res_ohm: 1d; SizeX_mm: 5; SizeY_mm: 2.5; SizeZ_mm: 1.66; SizeArea_mm2: 12.5; VDC_V: 0V; AEC Category: Q200
R7 = CMP-0023301-5: RES, 86.6 k, 1%, 0.1 W, 0603; Manufacturer: Yageo; Power_W: 100mW; TempCo: 100 ppm/C; Value_Code: 86k6; Value: 86.6k; EIA_Code: E96; SizeX_mm: 1.6; SizeY_mm: 0.8; SizeZ_mm: 1; Value2: 0.1W; SizeArea_mm2: 1.28; AEC Qualified: N; VDC_V: 75V; AEC Category: Q200; SizeAreaWB_mm2: 4.68
R8 R11 = CMP-0080488-1: RES, 10.0 k, 1%, 0.1 W, 0603; Manufacturer: TT Electronics/IRC; Power_W: 100mW; TempCo: 100 ppm/C; SizeAreaWB_mm2: 4.68; Value_Code: 10k0; Value: 10.0k; EIA_Code: E96; Res_ohm: 10k; SizeX_mm: 1.6; SizeY_mm: 0.8; SizeZ_mm: 1; Value2: 0.1W; SizeArea_mm2: 1.28; AEC Qualified: N; AEC Category: Q200
R12 R17 = CMP-0022965-5: RES, 27.4 k, 1%, 0.1 W, 0603; Manufacturer: Yageo; Power_W: 100mW; TempCo: 100 ppm/C; Value_Code: 27k4; Value: 27.4k; EIA_Code: E96; SizeX_mm: 1.6; SizeY_mm: 0.8; SizeZ_mm: 1; Value2: 0.1W; SizeArea_mm2: 1.28; AEC Qualified: N; VDC_V: 75V; AEC Category: Q200; SizeAreaWB_mm2: 4.68
R13 = CMP-0020156-2: RES, 51.1, 0.1%, 0.125 W, 0805; PartNumber: RT0805BRD0751R1L; Manufacturer: Yageo America; Value: 51.1; Value_Code: 51R1; Power_W: 125mW; Value2: 0.125W; VDC_V: 150V; TempCo: 25 ppm/C; SizeArea_mm2: 2.5; SizeX_mm: 2; SizeY_mm: 1.25; SizeZ_mm: 1.45; EIA_Code: E192; U/M: EA; AEC Category: Q200
R14 R18 R22 = CMP-0021139-3: RES, 2.87 M, 1%, 0.125 W, AEC-Q200 Grade 0, 0805; PartNumber: CRCW08052M87FKEA; Manufacturer: Vishay-Dale; Value: 2.87Meg; Value_Code: 2M87; Power_W: 125mW; Value2: 0.125W; VDC_V: 150V; TempCo: 100 ppm/C; SizeArea_mm2: 2.5; SizeX_mm: 2; SizeY_mm: 1.25; SizeZ_mm: 1.45; EIA_Code: E96; AEC Category: Q200; AEC Qualified: Y; AEC Grade: 0
R15 R16 R20 R21 R23 = CMP-0021137-3: RES, 2.74 M, 1%, 0.125 W, AEC-Q200 Grade 0, 0805; PartNumber: CRCW08052M74FKEA; Manufacturer: Vishay-Dale; Value: 2.74Meg; Value_Code: 2M74; Power_W: 125mW; Value2: 0.125W; VDC_V: 150V; TempCo: 100 ppm/C; SizeArea_mm2: 2.5; SizeX_mm: 2; SizeY_mm: 1.25; SizeZ_mm: 1.45; EIA_Code: E96; AEC Category: Q200; AEC Qualified: Y; AEC Grade: 0
R19 = CMP-0023070-4: RES, 392 k, 1%, 0.1 W, 0603; Manufacturer: Yageo; Power_W: 100mW; TempCo: 100 ppm/C; Value: 392k; EIA_Code: E96; SizeX_mm: 1.6; SizeY_mm: 0.8; SizeZ_mm: 1; Value2: 0.1W; SizeArea_mm2: 1.28; AEC Qualified: N; VDC_V: 75V; AEC Category: Q200; SizeAreaWB_mm2: 4.68
R24 = CMP-0020835-3: RES, 100, 1%, 0.125 W, AEC-Q200 Grade 0, 0805; PartNumber: CRCW0805100RFKEA; Manufacturer: Vishay-Dale; Value: 100; Value_Code: 100R; Power_W: 125mW; Value2: 0.125W; VDC_V: 150V; TempCo: 100 ppm/C; SizeArea_mm2: 2.5; SizeX_mm: 2; SizeY_mm: 1.25; SizeZ_mm: 1.45; EIA_Code: E96; AEC Category: Q200; AEC Qualified: Y; AEC Grade: 0
R25 R37 = CMP-0020881-3: RES, 133 k, 1%, 0.125 W, AEC-Q200 Grade 0, 0805; Manufacturer: Vishay-Dale; Power_W: 125mW; TempCo: 100 ppm/C; Value: 133k; EIA_Code: E96; SizeX_mm: 2; SizeY_mm: 1.25; SizeZ_mm: 1.45; Value2: 0.125W; SizeArea_mm2: 2.5; AEC Qualified: Y; VDC_V: 150V; AEC Category: Q200; AEC Grade: 0
R26 = CMP-0021817-2: RES, 9.53 k, 1%, 0.125 W, 0805; PartNumber: ERJ-6ENF9531V; Manufacturer: Panasonic; Value: 9.53k; Value_Code: 9k53; Power_W: 125mW; Value2: 0.125W; TempCo: 100 ppm/C; SizeArea_mm2: 2.5; SizeX_mm: 2; SizeY_mm: 1.25; SizeZ_mm: 1.45; EIA_Code: E96; U/M: EA; AEC Category: Q200
R27 = CMP-0021219-4: RES, 3.01 M, 1%, 0.125 W, AEC-Q200 Grade 0, 0805; PartNumber: CRCW08053M01FKEA; Manufacturer: Vishay-Dale; Value: 3.01Meg; Value_Code: 3M01; Power_W: 125mW; Value2: 0.125W; VDC_V: 150V; TempCo: 100 ppm/C; SizeArea_mm2: 2.5; SizeX_mm: 2; SizeY_mm: 1.25; SizeZ_mm: 1.45; EIA_Code: E96; AEC Category: Q200; AEC Qualified: Y; AEC Grade: 0
R28 = CMP-0022095-4: RES, 187 k, 1%, 0.1 W, AEC-Q200 Grade 0, 0603; Manufacturer: Vishay-Dale; Power_W: 100mW; TempCo: 100 ppm/C; Value: 187k; EIA_Code: E96; SizeX_mm: 1.6; SizeY_mm: 0.8; SizeZ_mm: 1; Value2: 0.1W; SizeArea_mm2: 1.28; AEC Qualified: Y; VDC_V: 75V; AEC Category: Q200; AEC Grade: 0
R29 R35 R36 = CMP-0093609-1: 0Ω ±0 0.25W 1206 Thick Film Chip Resistor AEC-Q200 compliant; Manufacturer: Stackpole Electronics; AEC Qualified: Yes; VDC_V: 200V; AEC Grade: Grade 0; Power_W: 250mW; SizeZ_mm: 0.7mm
R30 R33 R34 = CMP-0023000-5: RES, 2.00 k, 1%, 0.1 W, 0603; Manufacturer: Yageo; Power_W: 100mW; TempCo: 100 ppm/C; Value_Code: 2k00; Value: 2.00k; EIA_Code: E96; Res_ohm: 2k; SizeX_mm: 1.6; SizeY_mm: 0.8; SizeZ_mm: 1; Value2: 0.1W; SizeArea_mm2: 1.28; AEC Qualified: N; VDC_V: 75V; AEC Category: Q200; SizeAreaWB_mm2: 4.68
R31 = CMP-0022931-4: RES, 237 k, 1%, 0.1 W, 0603; Manufacturer: Yageo; Power_W: 100mW; TempCo: 100 ppm/C; Value: 237k; EIA_Code: E96; SizeX_mm: 1.6; SizeY_mm: 0.8; SizeZ_mm: 1; Value2: 0.1W; SizeArea_mm2: 1.28; AEC Qualified: N; VDC_V: 75V; AEC Category: Q200; SizeAreaWB_mm2: 4.68
R32 = CMP-0020909-3: RES, 15.0 k, 1%, 0.125 W, AEC-Q200 Grade 0, 0805; Manufacturer: Vishay-Dale; Power_W: 125mW; TempCo: 100 ppm/C; Value_Code: 15k0; Value: 15.0k; EIA_Code: E96; Res_ohm: 15k; SizeX_mm: 2; SizeY_mm: 1.25; SizeZ_mm: 1.45; Value2: 0.125W; SizeArea_mm2: 2.5; AEC Qualified: Y; VDC_V: 150V; AEC Category: Q200; AEC Grade: 0
R38 = CMP-0020881-3: RES, 133 k, 1%, 0.125 W, AEC-Q200 Grade 0, 0805; PartNumber: CRCW0805133KFKEA; Manufacturer: Vishay-Dale; Value: 133k; Power_W: 125mW; Value2: 0.125W; VDC_V: 150V; TempCo: 100 ppm/C; SizeArea_mm2: 2.5; SizeX_mm: 2; SizeY_mm: 1.25; SizeZ_mm: 1.45; EIA_Code: E96; AEC Category: Q200; AEC Qualified: Y; AEC Grade: 0
R39 = CMP-0021455-3: RES, 82.5 k, 1%, 0.125 W, AEC-Q200 Grade 0, 0805; PartNumber: CRCW080582K5FKEA; Manufacturer: Vishay-Dale; Value: 82.5k; Value_Code: 82k5; Power_W: 125mW; Value2: 0.125W; VDC_V: 150V; TempCo: 100 ppm/C; SizeArea_mm2: 2.5; SizeX_mm: 2; SizeY_mm: 1.25; SizeZ_mm: 1.45; EIA_Code: E96; AEC Category: Q200; AEC Qualified: Y; AEC Grade: 0
R40 = CMP-0015864-3: RES, 0, 5%, 1 W, AEC-Q200 Grade 0, 2512; PartNumber: CRCW25120000Z0EG; Manufacturer: Vishay-Dale; Value: 0; Value_Code: 0000; Power_W: 1W; TempCo: ppm/C; SizeArea_mm2: 20.16; SizeX_mm: 6.3; SizeY_mm: 3.2; SizeZ_mm: 0.71; EIA_Code: E24; AEC Category: Q200; AEC Qualified: Y
RT1 = CMP-0002550-2: Thermistor NTC, 10 ohm, 20%, 8.5mm Disc; Manufacturer: TDK; TaMax_C: 175°C; TaMin_C: -55°C; Power_W: 1.4W; U/M: EA
RV1 = CMP-0002100-2: Varistor 275V RMS 10MM Radial, TH; PartNumber: S10K275E2; Manufacturer: TDK; SizeAreaWB_mm2: 103.6; SizeArea_mm2: 64.8; SizeX_mm: 12; SizeY_mm: 5.4; SizeZ_mm: 14.5
T1 T2 = CMP-0120250-1: PFCINDUCTOR PMP23428 683W; Manufacturer: Renco Electronics; DCR_ohm: 18m; Ind_H: 85µH; Ns1toNp: 1:0.2; SizeZ_mm: 0.39inch; AEC Qualified: No
TP1 TP3 = CMP-0055147-2: Test Point, Multipurpose, Red, TH; Manufacturer: Keystone Electronics; CT: TRUE; ContactFinish: Silver; Green_Lifecycle: Active; CNHeader: FALSE; Green_REACh: Passed
TP2 TP4 = CMP-0055148-2: Test Point, Multipurpose, Black, TH; Manufacturer: Keystone Electronics; CNHeader: FALSE; ContactFinish: Silver; Green_REACh: Passed; Green_Lifecycle: Active; CT: TRUE
TP5 = CMP-0055139-1: Test Point, Miniature, White, TH; Manufacturer: Keystone; CNHeader: FALSE; Green_Lifecycle: Active; Green_REACh: Passed; ContactFinish: Silver; CT: TRUE
U1 = CMP-0089843-1: Linear Voltage Regulator IC 1 Output 200mA SOT-23-5; Manufacturer: Texas Instruments; Output Type: AdjustableProgrammable; Accuracy Percentage: 2%; AEC Qualified: No; Max Supply Voltage: 18V; Dropout Voltage: 160mV; SizeZ_mm: 1.45mm; Output Voltage: 1.24-17.75V; Min Supply Voltage: 2.4V; TJmax_C: +125°C; Nominal Supply Current: 2uA; Number Of Outputs: 1; Standoff Height: 0mm
U2 = CMP-0065070-4: Manufacturer: Texas Instruments; SizeX_mm: 6.0; SizeY_mm: 9.9; CompType: IC; SizeZ_mm: 1.75; SizeArea_mm2: 59.4; SizeAreaWB_mm2: 95.2; U/M: EA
